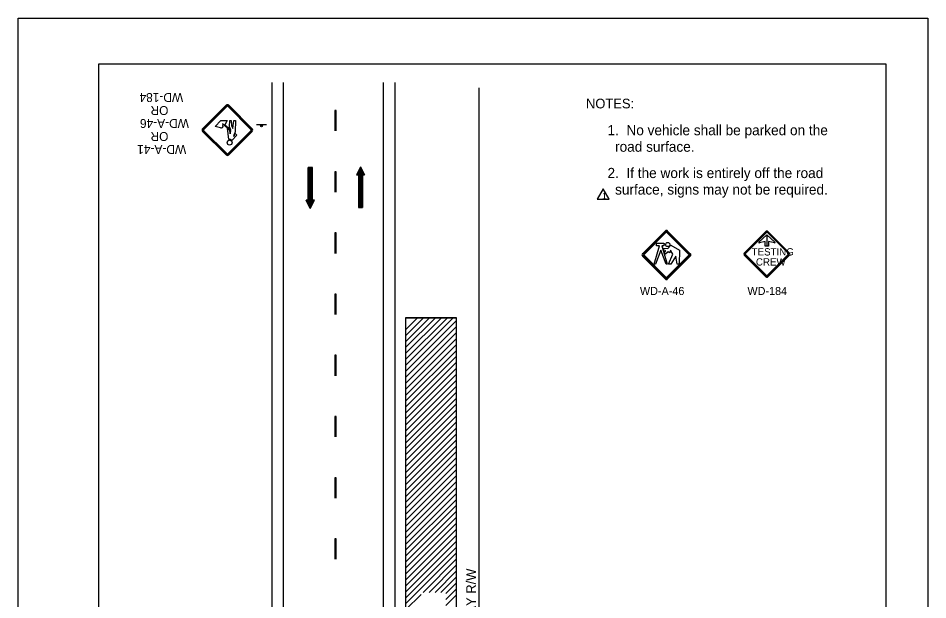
# Model space of a CAD drawing. Extents: x 1342 to 1558, y 178 to 457.
# Drawn here: x 1342.3 to 1558.3, y 318.9 to 456.9 of the extents above; entities that cross this region are included whole.
import ezdxf

# ---------------------------------------------------------------- set-up
doc = ezdxf.new("R2010")
doc.units = 0
for name, color, linetype in [('Level 1', 7, 'Continuous'), ('Level 10', 7, 'Continuous'), ('Level 2', 7, 'Continuous'), ('Level 22', 7, 'Continuous'), ('Level 3', 7, 'Continuous'), ('Level 44', 7, 'Continuous'), ('Level 60', 7, 'Continuous'), ('Level 61', 7, 'Continuous'), ('Level 62', 7, 'Continuous')]:
    doc.layers.add(name, color=color, linetype=linetype)

msp = doc.modelspace()

# ---------------------------------------------------------------- linework, layer by layer
at = {"layer": 'Level 1'}
for p, q in [((1391.65, 436.28), (1386.07, 430.71)), ((1391.78, 436.15), (1386.2, 430.58)), ((1391.9, 436.03), (1386.32, 430.46)), ((1397.61, 430.45), (1392.03, 436.03)), ((1397.73, 430.58), (1392.16, 436.15)), ((1397.86, 430.7), (1392.28, 436.28)), ((1386.07, 430.08), (1391.65, 424.5)), ((1386.2, 430.2), (1391.77, 424.63)), ((1386.32, 430.32), (1391.9, 424.75)), ((1392.03, 424.75), (1397.61, 430.32)), ((1392.15, 424.63), (1397.73, 430.2)), ((1392.28, 424.5), (1397.86, 430.07)), ((1392.22, 426.94), (1392.24, 426.94)), ((1490.52, 401.06), (1495.89, 406.44)), ((1490.66, 400.91), (1496.04, 406.29)), ((1490.81, 400.76), (1496.19, 406.14)), ((1496.16, 406.72), (1496.16, 406.72)), ((1496.2, 406.75), (1496.2, 406.75)), ((1496.2, 406.14), (1501.59, 400.76)), ((1496.35, 406.29), (1501.74, 400.91)), ((1496.5, 406.44), (1501.89, 401.06)), ((1514.7, 401.21), (1519.84, 406.34)), ((1519.93, 406.25), (1514.79, 401.11)), ((1514.79, 401.11), (1519.93, 406.25)), ((1514.88, 401.02), (1520.02, 406.16)), ((1520.12, 406.16), (1525.26, 401.02)), ((1520.31, 406.34), (1525.45, 401.21)), ((1520.07, 405.52), (1520.07, 402.87)), ((1495.89, 395.07), (1490.51, 400.45)), ((1496.04, 395.22), (1490.66, 400.6)), ((1496.19, 395.37), (1490.81, 400.75)), ((1496.16, 400.65), (1496.16, 400.65)), ((1501.59, 400.75), (1496.2, 395.37)), ((1501.74, 400.6), (1496.35, 395.22)), ((1501.89, 400.45), (1496.5, 395.07)), ((1519.84, 395.59), (1514.7, 400.73)), ((1520.02, 395.78), (1514.88, 400.92)), ((1520.09, 395.81), (1525.23, 400.95)), ((1520.09, 395.81), (1525.23, 400.95)), ((1520.09, 395.81), (1525.23, 400.95)), ((1525.23, 400.95), (1520.09, 395.81)), ((1525.26, 400.92), (1520.12, 395.78)), ((1525.45, 400.73), (1520.31, 395.59)), ((1525.68, 400.97), (1525.68, 400.97))]:
    msp.add_line(p, q, dxfattribs=at)
for points in [[(1390.33, 430.88), (1389.05, 431.26), (1390.43, 432.66), (1391.89, 432.66), (1391.35, 431.61), (1392.76, 430.45), (1392.48, 431.19), (1392.52, 432.66), (1392.87, 432.66), (1392.93, 431.4), (1393.27, 430.76), (1393.45, 432.66), (1393.87, 432.66), (1393.82, 429.93), (1393.38, 428.83), (1393.69, 429.15)], [(1390.33, 430.88), (1389.05, 431.26), (1390.43, 432.66), (1391.89, 432.66), (1391.35, 431.61), (1392.76, 430.45), (1392.48, 431.19), (1392.52, 432.66), (1392.87, 432.66), (1392.93, 431.4), (1393.27, 430.76), (1393.45, 432.66), (1393.87, 432.66), (1393.82, 429.93), (1393.38, 428.83), (1393.69, 429.15)], [(1390.33, 430.88), (1389.05, 431.26), (1390.43, 432.66), (1391.89, 432.66), (1391.35, 431.61), (1392.76, 430.45), (1392.48, 431.19), (1392.52, 432.66), (1392.87, 432.66), (1392.93, 431.4), (1393.27, 430.76)], [(1393.27, 430.76), (1393.45, 432.66), (1393.87, 432.66), (1393.82, 429.93), (1393.71, 429.67), (1394.22, 429.19), (1393, 427.93)], [(1392.3, 428.11), (1392.02, 430.83), (1392.38, 430.53), (1392.59, 429.52), (1392.76, 430.23), (1390.77, 431.86), (1390.91, 431.51)], [(1392.3, 428.11), (1392.02, 430.83), (1392.38, 430.53), (1392.59, 429.52), (1392.76, 430.23), (1390.77, 431.86), (1390.91, 431.51)], [(1392.3, 428.11), (1392.02, 430.83), (1390.77, 431.86), (1390.91, 431.51)], [(1393.69, 429.15), (1393.55, 429.26), (1393.71, 429.67), (1394.22, 429.19), (1393, 427.93)], [(1393.69, 429.15), (1393.55, 429.26), (1393.71, 429.67), (1394.22, 429.19), (1393, 427.93)]]:
    msp.add_lwpolyline(points, dxfattribs=at)
for points in [[(1392.38, 430.53), (1392.59, 429.52), (1392.76, 430.23)], [(1393.69, 429.15), (1393.55, 429.26), (1393.38, 428.83)], [(1481.17, 416.47), (1479.75, 414), (1482.59, 414)], [(1494.55, 402.94), (1493.89, 402.94), (1493.89, 403.58), (1495.62, 403.58), (1495.62, 403.49), (1495.7, 403.49), (1495.7, 403.23), (1495.62, 403.23), (1495.62, 402.94), (1495.14, 402.94), (1496.41, 398.61), (1496.13, 398.61), (1494.89, 401.88), (1493.64, 398.61), (1493.31, 398.61)], [(1494.55, 402.94), (1493.89, 402.94), (1493.89, 403.58), (1495.62, 403.58), (1495.62, 403.49), (1495.7, 403.49), (1495.7, 403.23), (1495.62, 403.23), (1495.62, 402.94), (1495.14, 402.94), (1496.41, 398.61), (1496.13, 398.61), (1494.89, 401.88), (1493.64, 398.61), (1493.31, 398.61)], [(1495.6, 402.34), (1496.51, 402.26), (1497.23, 403.08), (1499.28, 401.89), (1499.21, 398.61), (1498.73, 398.61), (1498.42, 400.49), (1497.23, 398.61), (1496.69, 398.61), (1497.71, 400.94), (1497.17, 401.88), (1497.06, 401.3), (1496.59, 401.49), (1496.01, 400.94), (1495.66, 401.27), (1496.04, 401.72), (1495.52, 401.96)], [(1495.6, 402.34), (1496.51, 402.26), (1497.23, 403.08), (1499.28, 401.89), (1499.21, 398.61), (1498.73, 398.61), (1498.42, 400.49), (1497.23, 398.61), (1496.69, 398.61), (1497.71, 400.94), (1497.17, 401.88), (1497.06, 401.3), (1496.59, 401.49), (1496.01, 400.94), (1495.66, 401.27), (1496.04, 401.72), (1495.52, 401.96)]]:
    msp.add_lwpolyline(points, close=True, dxfattribs=at)
msp.add_circle((1392.49, 427.4), 0.591, dxfattribs=at)
msp.add_circle((1392.49, 427.4), 0.591, dxfattribs=at)
msp.add_circle((1392.49, 427.4), 0.591, dxfattribs=at)
for centre, radius, start, end in [((1391.97, 435.96), 0.446, 45, 134.9652), ((1391.97, 435.96), 0.27, 45, 134.9652), ((1391.97, 435.96), 0.0948, 45, 134.9652), ((1386.39, 430.39), 0.446, 134.9651, 225), ((1386.39, 430.39), 0.27, 134.9651, 225), ((1386.39, 430.39), 0.0948, 134.9651, 225), ((1390.47, 431.34), 0.475, 253.381, 21.0999), ((1390.47, 431.34), 0.475, 253.381, 21.0999), ((1390.47, 431.34), 0.475, 253.381, 21.0999), ((1397.54, 430.39), 0.0948, 314.965, 45), ((1397.54, 430.39), 0.27, 314.965, 45), ((1397.54, 430.39), 0.446, 314.965, 45), ((1392.49, 427.4), 0.734, 46.3135, 104.9576), ((1392.49, 427.4), 0.734, 46.3135, 104.9576), ((1392.49, 427.4), 0.734, 46.3135, 104.9576), ((1391.96, 424.82), 0.446, 225, 314.9651), ((1391.96, 424.82), 0.27, 225, 314.9651), ((1391.96, 424.82), 0.0948, 225, 314.9651), ((1496.2, 406.14), 0.43, 45.0349, 135), ((1496.2, 406.14), 0.218, 45.0349, 135), ((1496.2, 406.14), 0.00655, 45.0349, 135), ((1520.07, 406.11), 0.336, 44.9995, 135.0002), ((1520.07, 406.11), 0.204, 44.9995, 135.0002), ((1520.07, 406.11), 0.204, 44.9995, 135.0002), ((1520.07, 406.11), 0.0714, 44.9995, 135.0002), ((1520.07, 406.11), 0.0273, 45, 135), ((1520.07, 406.11), 0.0273, 45, 135), ((1520.07, 406.11), 0.0273, 45, 135), ((1490.82, 400.76), 0.43, 135, 224.9651), ((1490.82, 400.76), 0.218, 135, 224.9651), ((1490.82, 400.76), 0.00655, 135, 224.9651), ((1501.58, 400.76), 0.00655, 315, 45.0346), ((1501.58, 400.76), 0.218, 315, 45.0346), ((1501.58, 400.76), 0.43, 315, 45.0346), ((1514.93, 400.97), 0.336, 135.0005, 225), ((1514.93, 400.97), 0.204, 135.0005, 225), ((1514.93, 400.97), 0.204, 135.0005, 225), ((1514.93, 400.97), 0.204, 135.0005, 225), ((1514.93, 400.97), 0.0714, 135.0005, 225), ((1525.21, 400.97), 0.0273, 315, 45), ((1525.21, 400.97), 0.0273, 315, 45), ((1525.21, 400.97), 0.0273, 315, 45), ((1525.21, 400.97), 0.0714, 315.0005, 44.9999), ((1525.21, 400.97), 0.204, 315.0005, 44.9999), ((1525.21, 400.97), 0.204, 315.0005, 44.9999), ((1525.21, 400.97), 0.336, 315.0005, 44.9999), ((1496.2, 395.37), 0.00655, 224.965, 315), ((1520.07, 395.83), 0.336, 224.9995, 315), ((1520.07, 395.83), 0.0714, 224.9995, 315), ((1520.07, 395.83), 0.0273, 225, 315), ((1520.07, 395.83), 0.0273, 225, 315), ((1520.07, 395.83), 0.0273, 225, 315), ((1496.2, 395.37), 0.43, 224.965, 315), ((1496.2, 395.37), 0.218, 224.965, 315)]:
    msp.add_arc(centre, radius, start, end, dxfattribs=at)
at = {"layer": 'Level 10'}
for p, q in [((1402.52, 441.71), (1402.52, 425.37)), ((1405.24, 441.71), (1405.24, 425.37)), ((1428.95, 441.71), (1428.95, 425.37)), ((1431.69, 441.71), (1431.69, 425.37)), ((1451.69, 440.38), (1451.69, 195.81)), ((1402.52, 437.4), (1402.52, 437.4)), ((1402.52, 425.37), (1402.52, 373)), ((1405.24, 425.37), (1405.24, 373)), ((1428.95, 425.37), (1428.95, 373)), ((1431.69, 425.37), (1431.69, 373)), ((1411.17, 413.74), (1411.17, 421.48)), ((1412.14, 421.48), (1411.17, 421.48)), ((1411.17, 412.77), (1411.17, 421.48)), ((1411.29, 412.53), (1411.29, 421.48)), ((1411.41, 412.29), (1411.41, 421.48)), ((1411.53, 412.05), (1411.53, 421.48)), ((1411.65, 411.8), (1411.65, 421.48)), ((1411.77, 412.05), (1411.77, 421.48)), ((1411.89, 412.29), (1411.89, 421.48)), ((1412.02, 412.53), (1412.02, 421.48)), ((1412.14, 413.74), (1412.14, 421.48)), ((1412.14, 412.77), (1412.14, 421.48)), ((1423.57, 421.7), (1422.6, 419.76)), ((1423.33, 421.21), (1423.33, 412.02)), ((1423.45, 421.45), (1423.45, 412.02)), ((1423.57, 421.7), (1423.57, 412.02)), ((1423.57, 421.7), (1424.54, 419.76)), ((1423.69, 421.45), (1423.69, 412.02)), ((1423.81, 421.21), (1423.81, 412.02)), ((1422.6, 419.76), (1423.09, 419.76)), ((1422.73, 420), (1422.73, 419.76)), ((1422.85, 420.25), (1422.85, 419.76)), ((1422.97, 420.49), (1422.97, 419.76)), ((1423.09, 420.73), (1423.09, 412.02)), ((1423.09, 419.76), (1423.09, 412.02)), ((1423.21, 420.97), (1423.21, 412.02)), ((1423.93, 420.97), (1423.93, 412.02)), ((1424.06, 420.73), (1424.06, 412.02)), ((1424.06, 419.76), (1424.06, 412.02)), ((1424.06, 419.76), (1424.54, 419.76)), ((1424.18, 420.49), (1424.18, 419.76)), ((1424.3, 420.25), (1424.3, 419.76)), ((1424.42, 420), (1424.42, 419.76)), ((1411.65, 411.8), (1410.68, 413.74)), ((1411.17, 413.74), (1410.68, 413.74)), ((1410.81, 413.5), (1410.81, 413.74)), ((1410.93, 413.25), (1410.93, 413.74)), ((1411.05, 413.01), (1411.05, 413.74)), ((1411.65, 411.8), (1412.62, 413.74)), ((1412.62, 413.74), (1412.14, 413.74)), ((1412.26, 413.01), (1412.26, 413.74)), ((1412.38, 413.25), (1412.38, 413.74)), ((1412.5, 413.5), (1412.5, 413.74)), ((1423.09, 412.02), (1424.06, 412.02)), ((1434.29, 383.01), (1437.12, 385.84)), ((1434.29, 381.6), (1438.53, 385.84)), ((1434.29, 380.18), (1439.94, 385.84)), ((1434.29, 378.77), (1441.36, 385.84)), ((1434.29, 377.35), (1442.77, 385.84)), ((1434.29, 375.94), (1444.19, 385.84)), ((1434.29, 374.53), (1445.6, 385.84)), ((1434.29, 373.11), (1446.38, 385.21)), ((1434.29, 371.7), (1446.38, 383.79)), ((1434.29, 370.28), (1446.38, 382.38)), ((1434.29, 368.87), (1446.38, 380.96)), ((1434.29, 367.45), (1446.38, 379.55)), ((1434.29, 366.04), (1446.38, 378.13)), ((1434.29, 364.63), (1446.38, 376.72)), ((1434.29, 363.21), (1446.38, 375.31)), ((1434.29, 361.8), (1446.38, 373.89)), ((1402.52, 373), (1402.52, 195.81)), ((1405.24, 373), (1405.24, 195.81)), ((1428.95, 373), (1428.95, 195.81)), ((1431.69, 373), (1431.69, 195.81)), ((1434.29, 360.38), (1446.38, 372.48)), ((1434.29, 358.97), (1446.38, 371.06)), ((1434.29, 357.56), (1446.38, 369.65)), ((1434.29, 356.14), (1446.38, 368.24)), ((1434.29, 354.73), (1446.38, 366.82)), ((1434.29, 353.31), (1446.38, 365.41)), ((1434.29, 351.9), (1446.38, 363.99)), ((1434.29, 350.48), (1446.38, 362.58)), ((1434.29, 349.07), (1446.38, 361.16)), ((1434.29, 347.66), (1446.38, 359.75)), ((1434.29, 346.24), (1446.38, 358.34)), ((1434.29, 344.83), (1446.38, 356.92)), ((1434.29, 343.41), (1446.38, 355.51)), ((1434.29, 342), (1446.38, 354.09)), ((1434.29, 340.58), (1446.38, 352.68)), ((1434.29, 339.17), (1446.38, 351.26)), ((1434.29, 337.76), (1446.38, 349.85)), ((1434.29, 336.34), (1446.38, 348.44)), ((1434.29, 334.93), (1446.38, 347.02)), ((1434.29, 333.51), (1446.38, 345.61)), ((1434.29, 332.1), (1446.38, 344.19)), ((1434.29, 330.69), (1446.38, 342.78)), ((1434.29, 329.27), (1446.38, 341.37)), ((1434.29, 327.86), (1446.38, 339.95)), ((1434.29, 326.44), (1446.38, 338.54)), ((1434.29, 325.03), (1446.38, 337.12)), ((1434.29, 323.61), (1446.38, 335.71)), ((1434.29, 322.2), (1446.38, 334.29)), ((1434.29, 320.79), (1446.38, 332.88)), ((1434.29, 319.37), (1446.38, 331.47)), ((1434.29, 317.96), (1446.38, 330.05)), ((1438.44, 320.69), (1446.38, 328.64)), ((1439.85, 320.69), (1446.38, 327.22)), ((1441.27, 320.69), (1446.38, 325.81)), ((1442.68, 320.69), (1446.38, 324.39)), ((1443.82, 320.42), (1446.38, 322.98)), ((1434.29, 316.54), (1437.98, 320.24)), ((1443.82, 319), (1446.38, 321.57)), ((1443.82, 317.59), (1446.38, 320.15))]:
    msp.add_line(p, q, dxfattribs=at)
at = {"layer": 'Level 2'}
for p, q in [((1417.47, 435.01), (1417.47, 430.17)), ((1417.76, 435.01), (1417.47, 435.01)), ((1417.76, 430.17), (1417.76, 435.01)), ((1417.47, 420.49), (1417.47, 415.66)), ((1417.76, 420.49), (1417.47, 420.49)), ((1417.76, 415.66), (1417.76, 420.49)), ((1417.47, 405.98), (1417.47, 401.14)), ((1417.76, 405.98), (1417.47, 405.98)), ((1417.76, 401.14), (1417.76, 405.98)), ((1417.47, 391.47), (1417.47, 386.63)), ((1417.76, 391.47), (1417.47, 391.47)), ((1417.76, 386.63), (1417.76, 391.47)), ((1417.47, 376.95), (1417.47, 372.11)), ((1417.76, 376.95), (1417.47, 376.95)), ((1417.76, 372.11), (1417.76, 376.95)), ((1417.47, 362.44), (1417.47, 357.6)), ((1417.76, 362.44), (1417.47, 362.44)), ((1417.76, 357.6), (1417.76, 362.44)), ((1417.47, 347.92), (1417.47, 343.08)), ((1417.76, 347.92), (1417.47, 347.92)), ((1417.76, 343.08), (1417.76, 347.92)), ((1417.47, 333.41), (1417.47, 328.57)), ((1417.76, 333.41), (1417.47, 333.41)), ((1417.76, 328.57), (1417.76, 333.41))]:
    msp.add_line(p, q, dxfattribs=at)
for centre, radius, start, end in [((1520.07, 406.11), 0.336, 44.9995, 135.0002), ((1520.07, 406.11), 0.204, 44.9995, 135.0002), ((1514.93, 400.97), 0.336, 135.0005, 225), ((1525.21, 400.97), 0.204, 315.0005, 44.9999), ((1525.21, 400.97), 0.336, 315.0005, 44.9999), ((1520.07, 395.83), 0.204, 224.9995, 315)]:
    msp.add_arc(centre, radius, start, end, dxfattribs=at)
at = {"layer": 'Level 22'}
for p, q in [((1368.28, 446.11), (1548.28, 446.11)), ((1548.28, 446.11), (1548.28, 188.73))]:
    msp.add_line(p, q, dxfattribs=at)
at = {"layer": 'Level 3'}
for centre, start, end in [((1520.07, 406.11), 45, 135), ((1520.07, 406.11), 45, 135), ((1525.21, 400.97), 315, 45), ((1525.21, 400.97), 315, 45), ((1520.07, 395.83), 225, 315), ((1520.07, 395.83), 225, 315)]:
    msp.add_arc(centre, 0.0273, start, end, dxfattribs=at)
at = {"layer": 'Level 44'}
msp.add_line((1401.26, 431.65), (1398.84, 431.65), dxfattribs=at)
for centre, radius in [((1400.04, 431.38), 0.242), ((1400.04, 431.38), 0.121), ((1496.54, 403.23), 0.494), ((1496.54, 403.23), 0.494)]:
    msp.add_circle(centre, radius, dxfattribs=at)
at = {"layer": 'Level 60'}
for p, q in [((1342.28, 456.92), (1342.28, 456.92)), ((1518.29, 403.6), (1518.29, 403.6)), ((1434.29, 385.84), (1446.38, 385.84))]:
    msp.add_line(p, q, dxfattribs=at)
for points in [[(1342.28, 456.92), (1558.28, 456.92), (1558.28, 177.92), (1342.28, 177.92)], [(1361.41, 446.11), (1548.28, 446.11), (1548.28, 188.73), (1361.41, 188.73)], [(1446.38, 385.84), (1434.29, 385.84), (1434.29, 234.9), (1446.38, 234.9)]]:
    msp.add_lwpolyline(points, close=True, dxfattribs=at)
for points in [[(1518.18, 403.8), (1520.07, 405.52), (1521.96, 403.8)], [(1521.85, 403.6), (1520.46, 403.95), (1520.46, 402.87), (1519.68, 402.87), (1519.68, 403.95), (1518.29, 403.6)]]:
    msp.add_lwpolyline(points, dxfattribs=at)
for centre, start, end in [((1518.26, 403.71), 132.3048, 284.4075), ((1521.88, 403.71), 255.5925, 47.6952)]:
    msp.add_arc(centre, 0.119, start, end, dxfattribs=at)
at = {"layer": 'Level 61'}
msp.add_line((1518.29, 403.6), (1518.29, 403.6), dxfattribs=at)
for points in [[(1518.18, 403.8), (1520.07, 405.52), (1521.96, 403.8)], [(1521.85, 403.6), (1520.46, 403.95), (1520.46, 402.87), (1519.68, 402.87), (1519.68, 403.95), (1518.29, 403.6)]]:
    msp.add_lwpolyline(points, dxfattribs=at)
for centre, start, end in [((1518.26, 403.71), 132.3048, 284.4075), ((1521.88, 403.71), 255.5925, 47.6952)]:
    msp.add_arc(centre, 0.119, start, end, dxfattribs=at)
at = {"layer": 'Level 62'}
for p, q in [((1514.79, 401.11), (1519.93, 406.25)), ((1520.22, 406.25), (1525.35, 401.11)), ((1518.29, 403.6), (1518.29, 403.6)), ((1519.93, 395.69), (1514.79, 400.82)), ((1525.35, 400.82), (1520.22, 395.69))]:
    msp.add_line(p, q, dxfattribs=at)
for points in [[(1518.18, 403.8), (1520.07, 405.52), (1521.96, 403.8)], [(1521.85, 403.6), (1520.46, 403.95), (1520.46, 402.87), (1519.68, 402.87), (1519.68, 403.95), (1518.29, 403.6)]]:
    msp.add_lwpolyline(points, dxfattribs=at)
for centre, radius, start, end in [((1520.07, 406.11), 0.204, 44.9995, 135.0002), ((1518.26, 403.71), 0.119, 132.3048, 284.4075), ((1521.88, 403.71), 0.119, 255.5925, 47.6952), ((1514.93, 400.97), 0.204, 135.0005, 225), ((1525.21, 400.97), 0.204, 315.0005, 44.9999), ((1520.07, 395.83), 0.204, 224.9995, 315)]:
    msp.add_arc(centre, radius, start, end, dxfattribs=at)

# ---------------------------------------------------------------- texts
at = {"layer": 'Level 1'}
msp.add_text('1', height=1.45, rotation=360, dxfattribs=at).set_placement((1480.94, 414.06))
at = {"layer": 'Level 10'}
for s, height, rotation, p in [('WD-184', 2.115, 180, (1381.46, 439.16)), ('OR', 2.115, 180, (1377.95, 436.08)), ('WD-A-46', 2.115, 180, (1382.82, 433)), ('OR', 2.115, 180, (1377.95, 429.92)), ('WD-A-41', 2.115, 180, (1382.18, 426.84)), ('HIGHWAY R/W', 2.298, 90, (1450.97, 304.85))]:
    msp.add_text(s, height=height, rotation=rotation, dxfattribs=at).set_placement(p)
for s, height, p in [('NOTES:', 2.298, (1477.11, 435.53)), ('1.  No vehicle shall be parked on the ', 2.419, (1482.22, 429.16)), ('  road surface.', 2.419, (1482.22, 425.24)), ('2.  If the work is entirely off the road ', 2.419, (1482.22, 419)), ('  surface, signs may not be required.', 2.419, (1482.22, 415.08)), ('WD-A-46', 1.92, (1489.92, 391.25)), ('WD-184', 1.92, (1515.45, 391.25))]:
    msp.add_text(s, height=height, dxfattribs=at).set_placement(p)
at = {"layer": 'Level 62'}
for s, p in [('TESTING', (1516.45, 400.63)), ('CREW', (1517.47, 398.24))]:
    msp.add_text(s, height=1.728, rotation=360, dxfattribs=at).set_placement(p)

doc.saveas('drawing.dxf')
